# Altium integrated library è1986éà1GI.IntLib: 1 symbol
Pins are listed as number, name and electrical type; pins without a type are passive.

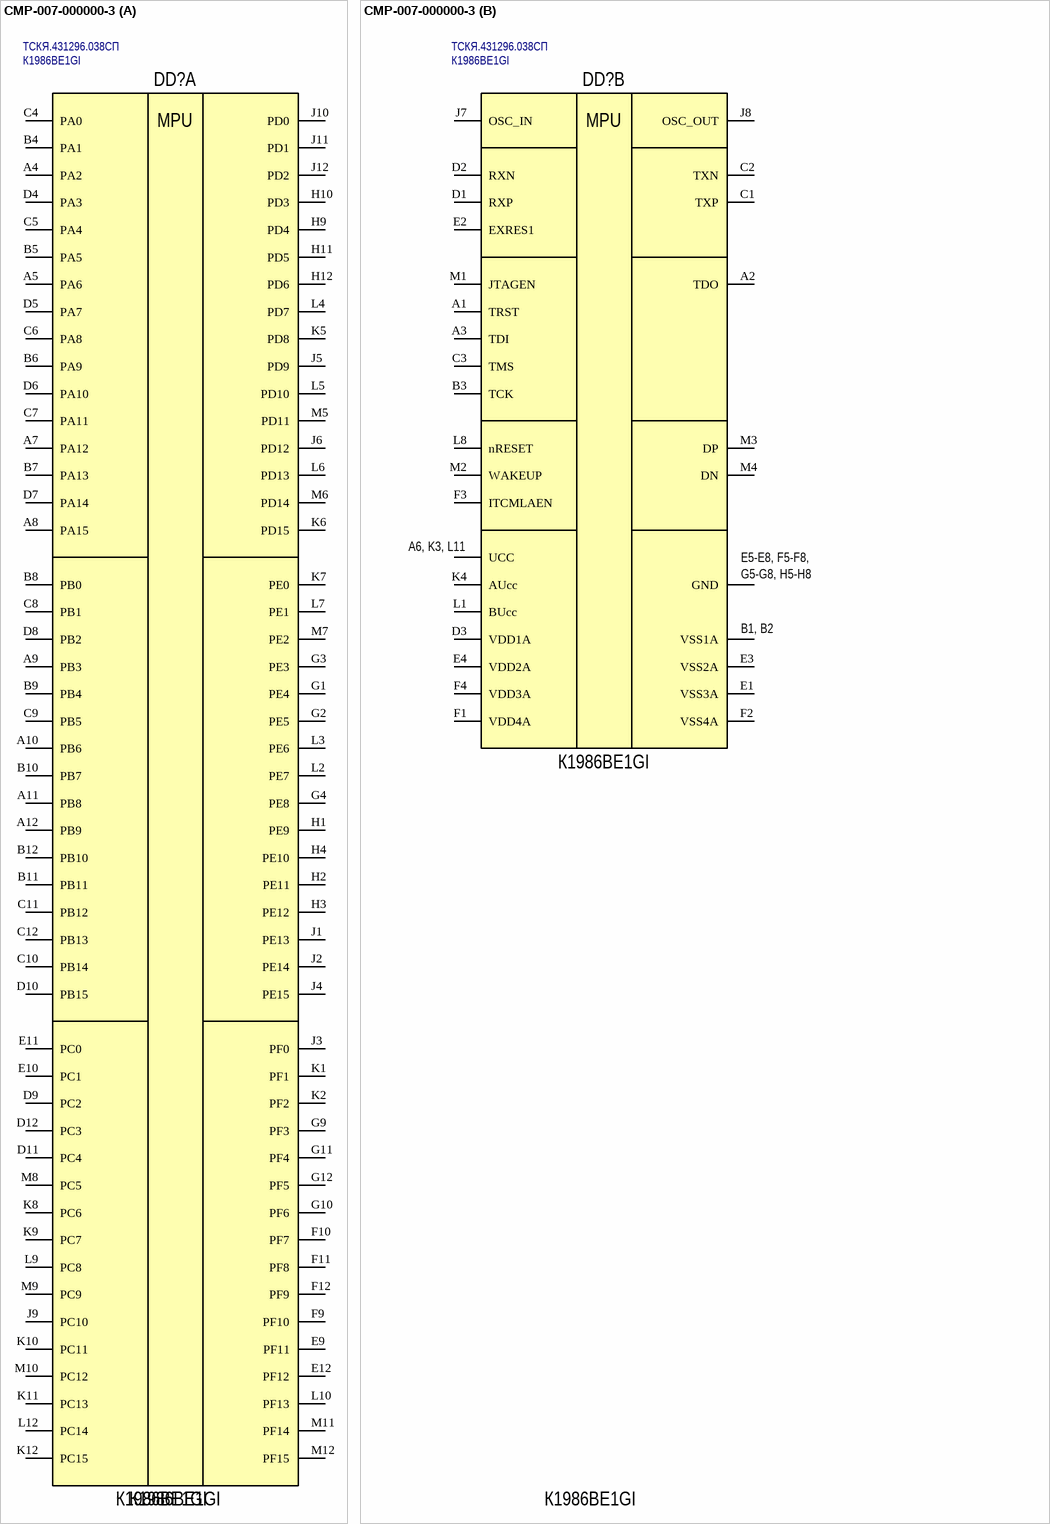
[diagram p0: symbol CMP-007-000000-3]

## CMP-007-000000-3
designator DD?, comment К1986ВЕ1GI  Decimal number: ТСКЯ.431296.038CП
Микросхема 32-разрядной микро-ЭВМ с Ethernet интерфейсом; Mark: MDR1213GI; Vendor: АО «ПКК Миландр»
footprint BGA144C127P12X12_1600X1600X220N (144-BGA, collapsing, 1.27 mm pitch, 16.00 X 16.00 X 2.20 mm body)
part A pins: A4 PA2, A5 PA6, A7 PA12, A8 PA15, A9 PB3, A10 PB6, A11 PB8, A12 PB9, B4 PA1, B5 PA5, B6 PA9, B7 PA13, B8 PB0, B9 PB4, B10 PB7, B11 PB11, B12 PB10, C4 PA0, C5 PA4, C6 PA8, C7 PA11, C8 PB1, C9 PB5, C10 PB14, C11 PB12, C12 PB13, D4 PA3, D5 PA7, D6 PA10, D7 PA14, D8 PB2, D9 PC2, D10 PB15, D11 PC4, D12 PC3, E9 PF11, E10 PC1, E11 PC0, E12 PF12, F9 PF10, F10 PF7, F11 PF8, F12 PF9, G1 PE4, G2 PE5, G3 PE3, G4 PE8, G9 PF3, G10 PF6, G11 PF4, G12 PF5, H1 PE9, H2 PE11, H3 PE12, H4 PE10, H9 PD4, H10 PD3, H11 PD5, H12 PD6, J1 PE13, J2 PE14, J3 PF0, J4 PE15, J5 PD9, J6 PD12, J9 PC10, J10 PD0, J11 PD1, J12 PD2, K1 PF1, K2 PF2, K5 PD8, K6 PD15, K7 PE0, K8 PC6, K9 PC7, K10 PC11, K11 PC13, K12 PC15, L2 PE7, L3 PE6, L4 PD7, L5 PD10, L6 PD13, L7 PE1, L9 PC8, L10 PF13, L12 PC14, M5 PD11, M6 PD14, M7 PE2, M8 PC5, M9 PC9, M10 PC12, M11 PF14, M12 PF15
part B pins: A1 TRST, A2 TDO, A3 TDI, A6 UСС, B1 VSS1A, B2 VSS1A, B3 TCK, C1 TXP, C2 TXN, C3 TMS, D1 RXP, D2 RXN, D3 VDD1A, E1 VSS3A, E2 EXRES1, E3 VSS2A, E4 VDD2A, E5 GND, E6 GND, E7 GND, E8 GND, F1 VDD4A, F2 VSS4A, F3 ITCMLAEN, F4 VDD3A, F5 GND, F6 GND, F7 GND, F8 GND, G5 GND, G6 GND, G7 GND, G8 GND, H5 GND, H6 GND, H7 GND, H8 GND, J7 OSC_IN, J8 OSC_OUT, K3 UСС, K4 AUcc, L1 BUcc, L8 nRESET, L11 UСС, M1 JTAGEN, M2 WAKEUP, M3 DP, M4 DN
